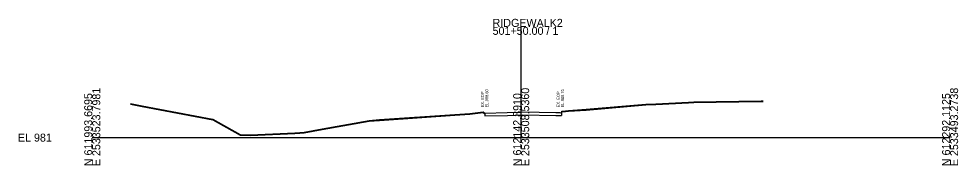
# Model space of a CAD drawing. Extents: x -26 to 303, y -23 to 1542.
# Drawn here: x -25.7 to 302.8, y 1490.3 to 1541.7 of the extents above; entities that cross this region are included whole.
import ezdxf

# ---------------------------------------------------------------- set-up
doc = ezdxf.new("R2010")
doc.units = 0
for name, color, linetype in [('DESIGN - SHEET - Light Grid', 7, 'Continuous'), ('SURVEY - GROUND - Bottom of Topsoil Layer', 7, 'Continuous'), ('SURVEY - GROUND - Existing Pavement Layer', 7, 'Continuous'), ('SURVEY - GROUND - Existing Pavement Text', 7, 'Continuous'), ('SURVEY - GROUND - Top of Ground', 7, 'Continuous')]:
    doc.layers.add(name, color=color, linetype=linetype)

msp = doc.modelspace()

# ---------------------------------------------------------------- linework, layer by layer
at = {"layer": 'DESIGN - SHEET - Light Grid'}
for p, q in [((150, 1500), (150, 1538.83)), ((0, 1500), (150, 1500)), ((150, 1500), (300, 1500))]:
    msp.add_line(p, q, dxfattribs=at)
at = {"layer": 'SURVEY - GROUND - Bottom of Topsoil Layer'}
for p, q in [((13.35, 1511.72), (17.42, 1510.94)), ((172.78, 1509.68), (193.58, 1511.44)), ((193.58, 1511.44), (197.04, 1511.59)), ((197.04, 1511.59), (208.54, 1512.23)), ((208.54, 1512.23), (210.44, 1512.29)), ((210.44, 1512.29), (233.89, 1512.69)), ((233.89, 1512.69), (234.67, 1512.64)), ((17.42, 1510.94), (42.13, 1506.18)), ((126.81, 1507.82), (132.04, 1508.22)), ((132.04, 1508.22), (136.67, 1508.83)), ((136.67, 1508.83), (137.24, 1508.34)), ((137.24, 1508.34), (137.24, 1508.59)), ((164.08, 1508.46), (164.27, 1509.08)), ((164.08, 1508.46), (164.08, 1508.71)), ((164.27, 1509.08), (165.54, 1509.14)), ((165.54, 1509.14), (166.57, 1509.23)), ((166.57, 1509.23), (172.78, 1509.68)), ((42.13, 1506.18), (44.07, 1505.13)), ((44.07, 1505.13), (51.75, 1500.82)), ((80.35, 1502.83), (96.89, 1505.8)), ((96.89, 1505.8), (100.51, 1506.05)), ((100.51, 1506.05), (126.81, 1507.82)), ((55.29, 1500.69), (70.87, 1501.46)), ((70.87, 1501.46), (72.65, 1501.54)), ((72.65, 1501.54), (74.1, 1501.65)), ((74.1, 1501.65), (80.35, 1502.83)), ((51.75, 1500.82), (55.29, 1500.69))]:
    msp.add_line(p, q, dxfattribs=at)
at = {"layer": 'SURVEY - GROUND - Existing Pavement Layer'}
for p, q in [((137.24, 1508.59), (137.24, 1507.59)), ((164.08, 1508.71), (164.08, 1507.75))]:
    msp.add_line(p, q, dxfattribs=at)
msp.add_lwpolyline([(137.24, 1507.59), (145.17, 1507.81), (150.53, 1507.99), (162.07, 1507.79), (164.08, 1507.75)], dxfattribs=at)
at = {"layer": 'SURVEY - GROUND - Top of Ground'}
msp.add_lwpolyline([(13.35, 1511.97), (17.42, 1511.19), (42.13, 1506.43), (44.07, 1505.38), (51.75, 1501.07), (55.29, 1500.94), (70.87, 1501.71), (72.65, 1501.79), (74.1, 1501.9), (80.35, 1503.08), (96.89, 1506.05), (100.51, 1506.3), (126.81, 1508.07), (132.04, 1508.47), (136.67, 1509.08), (137.24, 1508.59), (145.14, 1508.81), (150, 1508.97), (150.52, 1508.99), (162.09, 1508.78), (163.56, 1508.76), (164.08, 1508.71), (164.27, 1509.33), (165.54, 1509.39), (166.57, 1509.48), (172.78, 1509.93), (193.58, 1511.69), (197.04, 1511.84), (208.54, 1512.48), (210.44, 1512.54), (233.89, 1512.94), (234.67, 1512.89)], dxfattribs=at)

# ---------------------------------------------------------------- texts
at = {"layer": 'DESIGN - SHEET - Light Grid'}
for s, p in [('RIDGEWALK2', (140, 1538.83)), ('501+50.00 / 1', (140, 1536.03)), ('EL 981', (-26, 1498.6))]:
    msp.add_text(s, height=2.8, dxfattribs=at).set_placement(p)
for s, p in [('N 611993.6695', (0, 1490)), ('E 2533523.7981', (2.8, 1490)), ('N 612142.8910', (150, 1490)), ('E 2533508.5360', (152.8, 1490)), ('N 612292.1125', (300, 1490)), ('E 2533493.2738', (302.8, 1490))]:
    msp.add_text(s, height=2.8, rotation=90, dxfattribs=at).set_placement(p)
at = {"layer": 'SURVEY - GROUND - Existing Pavement Text'}
for s, p in [('EX. EOP', (136.97, 1510.66)), ('EL.988.60', (138.47, 1510.66)), ('EX. EOP', (163.47, 1510.66)), ('EL.988.75', (164.97, 1510.66))]:
    msp.add_text(s, height=1, rotation=90, dxfattribs=at).set_placement(p)

doc.saveas('drawing.dxf')
